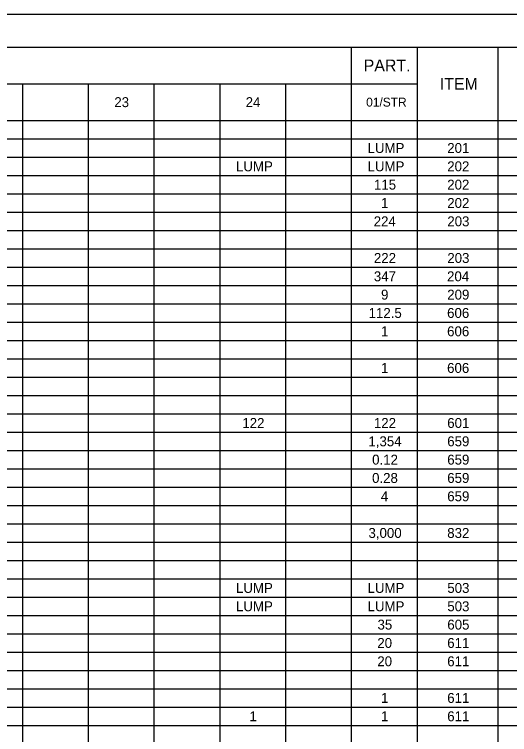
# Model space of a CAD drawing. Extents: x 0 to 34, y 0 to 35.
# Drawn here: x 9.42 to 16.98, y 11 to 22 of the extents above; entities that cross this region are included whole.
import ezdxf

# ---------------------------------------------------------------- set-up
doc = ezdxf.new("R2010")
doc.units = 0
for name, color, linetype in [('SH_Border', 7, 'Continuous'), ('SH_Cut_Line', 7, 'Continuous'), ('SH_Text', 7, 'Continuous')]:
    doc.layers.add(name, color=color, linetype=linetype)

msp = doc.modelspace()

# ---------------------------------------------------------------- linework, layer by layer
at = {"layer": 'SH_Border'}
msp.add_lwpolyline([(1.5, 21.5), (33.5, 21.5), (33.5, 0.5), (1.5, 0.5)], close=True, dxfattribs=at)
at = {"layer": 'SH_Cut_Line'}
msp.add_lwpolyline([(0, 0), (34, 0), (34, 22), (0, 22)], close=True, dxfattribs=at)
at = {"layer": 'SH_Text'}
for p, q in [((1.5, 21.5), (32.004, 21.5)), ((1.5, 21.5), (32.004, 21.5)), ((14.561, 21.5), (14.561, 0.5)), ((15.566, 21.5), (15.566, 0.5)), ((16.801, 21.5), (16.801, 0.5)), ((1.5, 20.94), (15.566, 20.94)), ((9.538, 20.94), (9.538, 0.5)), ((10.542, 20.94), (10.542, 0.5)), ((11.547, 20.94), (11.547, 0.5)), ((12.552, 20.94), (12.552, 0.5)), ((13.556, 20.94), (13.556, 0.5)), ((1.5, 20.38), (32.004, 20.38)), ((1.5, 20.1), (32.004, 20.1)), ((1.5, 19.82), (32.004, 19.82)), ((1.5, 19.54), (32.004, 19.54)), ((1.5, 19.26), (32.004, 19.26)), ((1.5, 18.98), (32.004, 18.98)), ((1.5, 18.7), (32.004, 18.7)), ((1.5, 18.42), (32.004, 18.42)), ((1.5, 18.14), (32.004, 18.14)), ((1.5, 17.86), (32.004, 17.86)), ((1.5, 17.58), (32.004, 17.58)), ((1.5, 17.3), (32.004, 17.3)), ((1.5, 17.02), (32.004, 17.02)), ((1.5, 16.74), (32.004, 16.74)), ((1.5, 16.46), (32.004, 16.46)), ((1.5, 16.18), (32.004, 16.18)), ((1.5, 15.9), (32.004, 15.9)), ((1.5, 15.62), (32.004, 15.62)), ((1.5, 15.34), (32.004, 15.34)), ((1.5, 15.06), (32.004, 15.06)), ((1.5, 14.78), (32.004, 14.78)), ((1.5, 14.5), (32.004, 14.5)), ((1.5, 14.22), (32.004, 14.22)), ((1.5, 13.94), (32.004, 13.94)), ((1.5, 13.66), (32.004, 13.66)), ((1.5, 13.38), (32.004, 13.38)), ((1.5, 13.1), (32.004, 13.1)), ((1.5, 12.82), (32.004, 12.82)), ((1.5, 12.54), (32.004, 12.54)), ((1.5, 12.26), (32.004, 12.26)), ((1.5, 11.98), (32.004, 11.98)), ((1.5, 11.7), (32.004, 11.7)), ((1.5, 11.42), (32.004, 11.42)), ((1.5, 11.14), (32.004, 11.14))]:
    msp.add_line(p, q, dxfattribs=at)

# ---------------------------------------------------------------- texts
for s, height, p in [('PART.', 0.1818, (14.75, 21.129)), ('ITEM', 0.1818, (15.912, 20.849)), ('23', 0.1515, (10.942, 20.584)), ('24', 0.1515, (12.948, 20.584)), ('01/STR', 0.1364, (14.788, 20.592)), ('LUMP', 0.1515, (14.809, 19.884)), ('201', 0.1515, (16.026, 19.884)), ('LUMP', 0.1515, (12.8, 19.604)), ('LUMP', 0.1515, (14.809, 19.604)), ('202', 0.1515, (16.026, 19.604)), ('115', 0.1515, (14.907, 19.324)), ('202', 0.1515, (16.026, 19.324)), ('1', 0.152, (15.015, 19.044)), ('202', 0.1515, (16.026, 19.044)), ('224', 0.1515, (14.903, 18.764)), ('203', 0.1515, (16.027, 18.764)), ('222', 0.1515, (14.906, 18.204)), ('203', 0.1515, (16.027, 18.204)), ('347', 0.1515, (14.905, 17.924)), ('204', 0.1515, (16.023, 17.924)), ('9', 0.152, (15.015, 17.644)), ('209', 0.1515, (16.026, 17.644)), ('112.5', 0.1515, (14.825, 17.364)), ('606', 0.1515, (16.024, 17.364)), ('1', 0.152, (15.015, 17.084)), ('606', 0.1515, (16.024, 17.084)), ('1', 0.152, (15.015, 16.524)), ('606', 0.1515, (16.024, 16.524)), ('122', 0.1515, (12.897, 15.684)), ('122', 0.1515, (14.906, 15.684)), ('601', 0.1515, (16.026, 15.684)), ('1,354', 0.1515, (14.822, 15.404)), ('659', 0.1515, (16.026, 15.404)), ('0.12', 0.1515, (14.879, 15.124)), ('659', 0.1515, (16.026, 15.124)), ('0.28', 0.1515, (14.878, 14.844)), ('659', 0.1515, (16.026, 14.844)), ('4', 0.152, (15.012, 14.564)), ('659', 0.1515, (16.026, 14.564)), ('3,000', 0.1515, (14.823, 14.004)), ('832', 0.1515, (16.026, 14.004)), ('LUMP', 0.1515, (12.8, 13.164)), ('LUMP', 0.1515, (14.809, 13.164)), ('503', 0.1515, (16.027, 13.164)), ('LUMP', 0.1515, (12.8, 12.884)), ('LUMP', 0.1515, (14.809, 12.884)), ('503', 0.1515, (16.027, 12.884)), ('35', 0.1515, (14.961, 12.604)), ('605', 0.1515, (16.027, 12.604)), ('20', 0.1515, (14.958, 12.324)), ('611', 0.1515, (16.026, 12.324)), ('20', 0.1515, (14.958, 12.044)), ('611', 0.1515, (16.026, 12.044)), ('1', 0.152, (15.015, 11.484)), ('611', 0.1515, (16.026, 11.484)), ('1', 0.152, (13.006, 11.204)), ('1', 0.152, (15.015, 11.204)), ('611', 0.1515, (16.026, 11.204))]:
    msp.add_text(s, height=height, dxfattribs=at).set_placement(p)

doc.saveas('drawing.dxf')
